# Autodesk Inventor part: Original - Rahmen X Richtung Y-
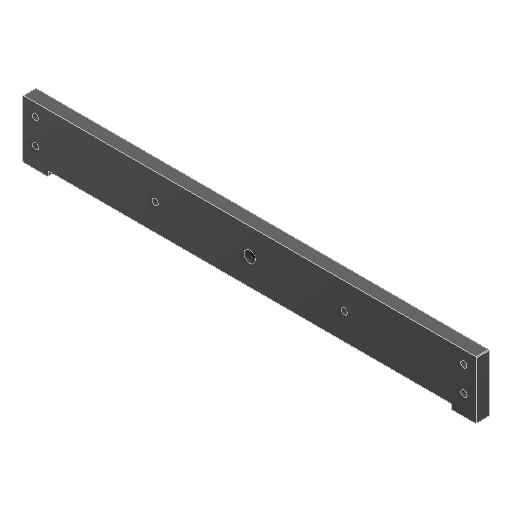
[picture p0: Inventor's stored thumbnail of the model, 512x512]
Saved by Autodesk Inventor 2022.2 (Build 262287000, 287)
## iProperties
Created: 2024-09
Part Number: Original - Rahmen X Richtung Y-
Material: Generico
Document SubType Name: Modeling
Designer: 18907419
Density: 1 g/cm^3
Appearance: Default
Author: 18907419
Revision Number: ANY
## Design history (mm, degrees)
feature "Schnitt-Linear austragen1"
node "Solido1"
